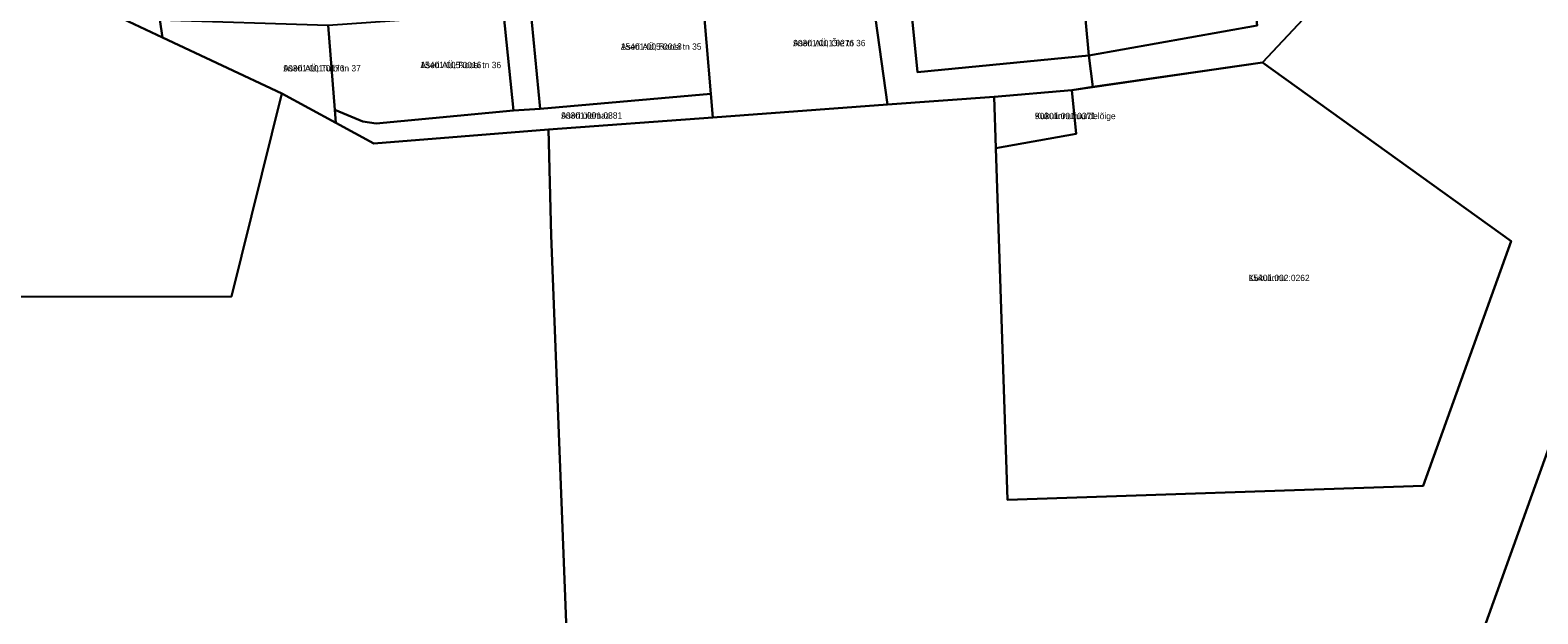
# Model space of a CAD drawing. Extents: x 634518 to 667988, y 6584667 to 6604739.
# Drawn here: x 663294.1 to 663652.2, y 6593025.8 to 6593164.3 of the extents above; entities that cross this region are included whole.
import ezdxf

# ---------------------------------------------------------------- set-up
doc = ezdxf.new("R2010")
doc.units = 0
for name, color, linetype in [('L_AADRESS', 7, 'Continuous'), ('PIIR', 7, 'Continuous'), ('TUNNUS', 7, 'Continuous')]:
    doc.layers.add(name, color=color, linetype=linetype)

msp = doc.modelspace()

# ---------------------------------------------------------------- linework, layer by layer
at = {"layer": 'PIIR'}
for points in [[(663292.72, 6593445.68), (663295.8, 6593418.01), (663298.53, 6593392.58), (663301.21, 6593369.07), (663304.06, 6593343.81), (663306.56, 6593319.62), (663309.02, 6593296.59), (663313.37, 6593277.64), (663314.03, 6593267.93), (663314.57, 6593260.23), (663317.41, 6593235.46), (663320.3, 6593210.74), (663322.7, 6593186.16), (663324.91, 6593166.71), (663325.51, 6593162.57), (663314.76, 6593167.62), (663307.64, 6593259.58), (663306, 6593266.08), (663301.52, 6593276.65), (663299.31, 6593294.15), (663297.12, 6593312.69), (663294.58, 6593332.19), (663291.86, 6593354.5)], [(663502.29, 6593179.87), (663504.87, 6593154.31), (663545.54, 6593158.28), (663546.5, 6593150.83), (663541.46, 6593150.08), (663523.06, 6593148.51), (663497.75, 6593146.66), (663493.44, 6593177.36)], [(663946.73, 6592894.66), (663669.25, 6592805.17), (663615.7, 6592838.09), (663580.25, 6592857.99), (663666.98, 6593099.13), (663768.37, 6593098.64), (663956.43, 6593093.78)]]:
    msp.add_lwpolyline(points, dxfattribs=at)
for points in [[(663381.19, 6593400.18), (663387.58, 6593404.14), (663388.77, 6593393.02), (663391.65, 6593367.66), (663393.68, 6593344.89), (663396.51, 6593320.66), (663398.75, 6593296.18), (663400.11, 6593284.48), (663401.77, 6593270.18), (663404.7, 6593244.75), (663407.53, 6593220.11), (663410.33, 6593193.95), (663412.81, 6593170.28), (663415.24, 6593145.66), (663408.9, 6593145.21), (663406.48, 6593168.39), (663403.48, 6593194.27), (663400.64, 6593219.67), (663397.91, 6593244.42), (663394.71, 6593278.08), (663392.83, 6593295.68), (663389.16, 6593328.51), (663386.48, 6593351.99), (663383.92, 6593376.29)], [(663565.44, 6593346.11), (663576.61, 6593345.66), (663582.91, 6593344.83), (663585.43, 6593308.12), (663591.11, 6593250.17), (663596.43, 6593166.89), (663586.76, 6593156.63), (663546.5, 6593150.83), (663545.54, 6593158.28), (663585.52, 6593165.42), (663582.85, 6593189.91), (663580.38, 6593214.67), (663577.24, 6593241), (663574.9, 6593264.66), (663572.1, 6593289.75), (663571.07, 6593299.19), (663568.79, 6593313.64), (663567, 6593332.22)], [(663307.64, 6593259.58), (663314.76, 6593167.62), (663325.51, 6593162.57), (663353.9, 6593149.24), (663341.95, 6593101.12), (663283.08, 6593101.01), (663025.91, 6593100.09), (663077.08, 6593196.44), (663087.61, 6593215.97), (663102.17, 6593217.97), (663215.16, 6593233.28), (663242.91, 6593239.18), (663243.54, 6593239.44), (663252.5, 6593243.18), (663290.65, 6593262), (663298.27, 6593264.58), (663304.39, 6593265.7), (663306, 6593266.08)], [(663417.18, 6593140.75), (663456.2, 6593143.61), (663497.75, 6593146.66), (663523.06, 6593148.51), (663523.47, 6593136.28), (663526.25, 6593052.89), (663624.97, 6593056.18), (663645.86, 6593114.27), (663586.76, 6593156.63), (663596.43, 6593166.89), (663688.91, 6593264.97), (663768.37, 6593098.64), (663666.98, 6593099.13), (663580.25, 6592857.99), (663615.7, 6592838.09), (663607.46, 6592739.74), (663604.16, 6592694.68), (663491.37, 6592703.11), (663392.51, 6592710.65), (663429.67, 6592795.74), (663425.58, 6592915.6), (663417.84, 6593115.56)], [(663545.54, 6593158.28), (663543.07, 6593185.11), (663582.85, 6593189.91), (663585.52, 6593165.42)], [(663504.87, 6593154.31), (663502.29, 6593179.87), (663543.07, 6593185.11), (663545.54, 6593158.28)], [(663456.2, 6593143.61), (663455.75, 6593149.21), (663453.7, 6593173.62), (663493.44, 6593177.36), (663497.75, 6593146.66)], [(663455.75, 6593149.21), (663415.24, 6593145.66), (663412.81, 6593170.28), (663453.7, 6593173.62)], [(663373.13, 6593142.64), (663366.48, 6593145.41), (663364.88, 6593165.47), (663406.48, 6593168.39), (663408.9, 6593145.21), (663376.24, 6593142.16)], [(663353.9, 6593149.24), (663325.51, 6593162.57), (663324.91, 6593166.71), (663364.88, 6593165.47), (663366.48, 6593145.41), (663366.71, 6593142.29)], [(663586.76, 6593156.63), (663645.86, 6593114.27), (663624.97, 6593056.18), (663526.25, 6593052.89), (663523.47, 6593136.28), (663542.56, 6593139.72), (663541.46, 6593150.08)], [(663542.56, 6593139.72), (663523.47, 6593136.28), (663523.06, 6593148.51), (663541.46, 6593150.08)], [(663279.65, 6593031.16), (663283.08, 6593101.01), (663341.95, 6593101.12), (663353.9, 6593149.24), (663366.71, 6593142.29), (663375.75, 6593137.39), (663417.18, 6593140.75), (663417.84, 6593115.56), (663425.58, 6592915.6), (663429.67, 6592795.74), (663392.51, 6592710.65), (663370.6, 6592844.18), (663271.65, 6592852.7), (663276.19, 6592955.77)], [(663455.75, 6593149.21), (663456.2, 6593143.61), (663417.18, 6593140.75), (663375.75, 6593137.39), (663366.71, 6593142.29), (663366.48, 6593145.41), (663373.13, 6593142.64), (663376.24, 6593142.16), (663408.9, 6593145.21), (663415.24, 6593145.66)]]:
    msp.add_lwpolyline(points, close=True, dxfattribs=at)

# ---------------------------------------------------------------- texts
at = {"layer": 'L_AADRESS'}
for s, p in [('Aseri AÜ, Roosi tn 35', (663434.37, 6593159.64)), ('Aseri AÜ, Õie tn 36', (663475.31, 6593160.49)), ('Aseri AÜ, Roosi tn 36', (663386.77, 6593155.28)), ('Aseri AÜ, Tulbi tn 37', (663354.23, 6593154.5)), ('Aseri üldmaa', (663420.21, 6593143.3)), ('Kukulinnu juurdelõige', (663532.72, 6593143.18)), ('Kukulinnu', (663583.48, 6593104.76))]:
    msp.add_text(s, height=1.5, dxfattribs=at).set_placement(p)
at = {"layer": 'TUNNUS'}
for s, p in [('15401:005:0018', (663434.37, 6593159.64)), ('90301:001:0276', (663475.31, 6593160.49)), ('90301:001:0176', (663354.23, 6593154.5)), ('15401:005:0016', (663386.77, 6593155.28)), ('90301:001:0381', (663420.21, 6593143.3)), ('90301:001:0371', (663532.72, 6593143.18)), ('15401:002:0262', (663583.48, 6593104.76))]:
    msp.add_text(s, height=1.5, dxfattribs=at).set_placement(p)

doc.saveas('drawing.dxf')
